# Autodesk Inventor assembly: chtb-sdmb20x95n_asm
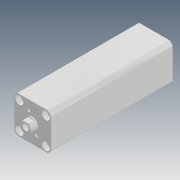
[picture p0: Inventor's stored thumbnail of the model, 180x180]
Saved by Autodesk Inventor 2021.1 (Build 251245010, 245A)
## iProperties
Company: Microsoft
Created: 2018-05
Part Number: chtb-sdmb20x95n_asm
Description: STEP AP214
Document SubType Name: Assembly
Designer: user
Title: chtb-sdmb20x95n_asm.STEP
Author: Windows
Revision Number: ÈÎºÎ
Sending System: SolidWorks 2015
Preprocessor: SwSTEP 2.0
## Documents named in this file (4)
- D:\Vault_2016\Projekty\Clamptek\Hydraulic\CHTB\CHTB-20\Inventor\CHTB-SDMB20x95N\chtb-sdmb20x95n_asm.iam
- D:\Vault_2016\Projekty\Clamptek\Hydraulic\CHTB\CHTB-20\Inventor\CHTB-SDMB20x95N\CHTB-SDMB20X95NBT.ipt
- D:\Vault_2016\Projekty\Clamptek\Hydraulic\CHTB\CHTB-20\Inventor\CHTB-SDMB20x95N\CHTB-SDMB20X95NHSG.ipt
- D:\Vault_2016\Projekty\Clamptek\Hydraulic\CHTB\CHTB-20\Inventor\CHTB-SDMB20x95N\QG_3.ipt
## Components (3 placed, 3 different names)
1. CHTB-SDMB20X95NBT_1
2. CHTB-SDMB20X95NHSG_2
3. QG_3_3
